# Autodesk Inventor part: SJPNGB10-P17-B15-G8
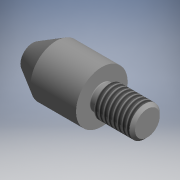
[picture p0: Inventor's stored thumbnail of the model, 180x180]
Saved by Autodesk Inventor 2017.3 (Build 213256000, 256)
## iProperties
Part Number: SJPNGB10-P17-B15-G8
Material: Generic
Catalog Web Link: www.cadenas.de
Description: JPNG, GJPNG, BJPNG, SJPNG-Screw - In Locating Pins - Full Threaded
Vendor: MISUMI
Document SubType Name: Modeling
Designer: partserver
Manufacturer: MISUMI
Mass: 5.48862 g
Surface Area: 19.2675 cm^2
Volume: 5.48862 cm^3
Density: 1 g/cm^3
Appearance: PSOLRGB-175-175-175
Category: PARTsolutions
Company: MISUMI
Title: SJPNGB10-P17-B15-G8
Author: Cadenas PARTsolutions
Comments: Screw - In Locating Pins - Full Threaded
PSOL_IDENT_0: {$CADENAS_DATA\23d-libs\misumi\metric\14_locating_pins\jpng.prj},252 {VTYP=3D},{NB=SJPNGB10-P17-B15-
PSOL_IDENT_1: G8},{LINA=SJPNGB10-P17-B15-G8},{NN=JPNG, GJPNG, BJPNG, SJPNG},{DATE=19.01.2022 02:35:35},{GEOMDATE=1
PSOL_IDENT_2: 3.01.2022 04:25:00},{VERSION=},{LINEID=70},{WBVAR=MAT,ST,HARD,TSS,P,B,R,G,ALT1,SC,ALT2,ALT3,S},{WBNU
PSOL_IDENT_3: MERIC=P,B,R,G,SC,S}  {NB=SJPNGB10-P17-B15-G8},{LINA=SJPNGB10-P17-B15-G8},{KT=DUMMY},{PN=SJPNGB10-P17
PSOL_IDENT_4: -B15-G8},{TYPE=SJPNG},{MAT=SUS304},{MATALG= 'SKS3','SKS3 Equivalent' , 'SUS304','SUS304' },{ST=-},{S
PSOL_IDENT_5: TALG= '-','-' },{HARD=-},{HARDALG= '-','-' },{TSS=B},{TSSALG= 'A' , 'B' , 'C' },{M=10},{P=17.0},{PAL
PSOL_IDENT_6: G=[11.0:17.0/0.1]},{B=15.0},{BALG=[3.0:30.0/0.1]},{R=0},{RALG=[0]},{RAMIN=9},{RAMAX=500},{RCMIN=1},{
PSOL_IDENT_7: RCMAX=8},{RPN=},{G=8},{GALG=[1:17/1]},{GMIN=1},{GMAX=17},{GPN=-G8},{X=17},{ALT1=},{ALT1ALG= '','w/o
PSOL_IDENT_8: SC (Wrench Flats)' , 'SC','with SC (Wrench Flats)' },{SC=0},{SCALG=[0]},{SCMIN=14},{SCMAX=16},{ALT1L
PSOL_IDENT_9: 3D=10},{ALT1PN=},{ALT2=},{ALT2ALG= '','w/o LAC (Wrench Hole(Dia. 3.5))' , 'LAC','with LAC (Wrench Ho
PSOL_IDENT_10: le(Dia. 3.5))' },{ALT2PN=},{ALT3=},{ALT3ALG= '','w/o RAC (Hex Socket Machining)' , 'RAC','with RAC (
PSOL_IDENT_11: Hex Socket Machining)' },{ALT3PN=},{S=0},{SALG=[0]},{SMAX=5},{E=0.0},{LL1=nan},{LL2=7.794229},{LL3=1
PSOL_IDENT_12: 4.722432},{LL3D=7.794229},{AA=2.5},{BB=7.7},{E1=2.3},{PITCH=1.5}
NB: SJPNGB10-P17-B15-G8
NN: JPNG, GJPNG, BJPNG, SJPNG
NT: Screw - In Locating Pins - Full Threaded
NBSYN: $PN.
LINA: SJPNGB10-P17-B15-G8
CATALOG: Misumi
PN: SJPNGB10-P17-B15-G8
MAT: SUS304
ST: -
HARD: -
TSS: B
M: 10
P: 17
B: 15
R: 0
G: 8
ALT1: w/o SC (Wrench Flats)
SC: 0
ALT2: w/o LAC (Wrench Hole(Dia. 3.5))
ALT3: w/o RAC (Hex Socket Machining)
S: 0
E: 0
AA: 2.5
BB: 7.7
SUPPLIER: MISUMI
ARTICLENO: SJPNGB10-P17-B15-G8
BOMINFO: SJPNGB10-P17-B15-G8
CREATOR: CADENAS GmbH
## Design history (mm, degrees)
sketch "Sketch_2"
  geometry: L1 (22.794, 0)-(0, 0); L2 (0, 0)-(0, 8.5); L3 (0, 8.5)-(15, 8.5); L4 (15, 8.5)-(22.794, 4); L5 (22.794, 4)-(22.794, 0); L6 (22.794, 0)-(0, 0)
  constraints: 12 end point
revolve "Revolution1" sketch "Sketch_2" stored, may be unused: angle "d0" = 360 deg
sketch "Sketch_6"
  geometry: L1 (0, 0)-(-15, 0); L2 (-15, 0)-(-15, 4.08); L3 (-15, 4.08)-(-14.08, 5); L4 (-14.08, 5)-(-2.5, 5); L5 (-2.5, 5)-(-2.5, 4.05); L6 (-2.3, 3.85)-(-0.2, 3.85); L7 (0, 4.05)-(0, 0); L8 (0, 0)-(-15, 0); A1 r 0.2 centre (-2.3, 4.05) between (-2.5, 4.05) and (-2.3, 3.85); A2 r 0.2 centre (-0.2, 4.05) between (-0.2, 3.85) and (0, 4.05)
  constraints: 16 end point, 4 point on circle, 2 centre point
revolve "Revolution2" sketch "Sketch_6" stored, may be unused: angle "d1" = 360 deg
thread "Thread1" dims "d2" = 11.58, "d3" = 0
node "to_base_XY"
node "to_base_YZ"
node "to_base_ZX"
node "to_base_X"
node "to_base_Y"
node "to_base_Z"
node "to_base_Center"
body "Solid1"
other parameters: "d4" = 0
